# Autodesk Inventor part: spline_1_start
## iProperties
Created: 2009-04
Part Number: spline_1_start
Document SubType Name: Modeling
Designer: PN
Density: 1 g/cm^3
Author: PN
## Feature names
1. Extrusion1
